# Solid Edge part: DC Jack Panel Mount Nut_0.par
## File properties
Last saved by: morva
Revision: 76
Accuracy: 0.990
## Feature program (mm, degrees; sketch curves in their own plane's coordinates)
body "unnamed Body 1"
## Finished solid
Body 1: solid body, 11 faces, 22 edges, 12 vertices.
  Faces by surface: plane 8, torus 2, cylinder 1
  Edges by curve: intersection 12, line 6, circle 4
Bounding box of the edges (mm; curved faces can reach further): 12.702 x 11.000 x 2.165, from (-6.3509, -5.5, -1.0827) to (6.3509, 5.5, 1.0827).
Cylindrical faces by radius (mm): R3.4544 x1
Toroidal faces (ring radius, tube radius in mm): R5.2236 r1.5 x2
Planar faces by outward normal: +y 1, +z 1, -y 1, -z 1, oblique 4
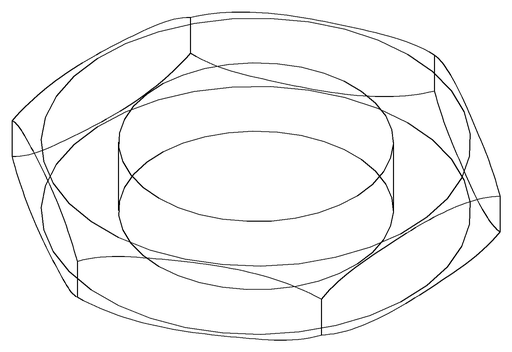
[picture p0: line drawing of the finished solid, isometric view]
